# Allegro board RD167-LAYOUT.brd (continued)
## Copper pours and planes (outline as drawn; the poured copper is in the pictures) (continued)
HV_DC_P on CONDUCTIVE5: outline of 196 points within 1,1 132.5,263 ; 26 cut-outs
LV_DC_N on BOTTOM (solid shape): 226.31,61.38 226.18,62.07 226.87,62.21 228.11,61.38 228.34,60.96 228.11,60.55 226.87,59.72 226.36,59.69 226.09,60.13 226.15,60.37 226.31,60.55 226.4,60.61 226.4,61.32
LV_DC_N on BOTTOM (solid shape): 226.31,28.38 226.18,29.07 226.87,29.21 228.11,28.38 228.34,27.96 228.11,27.55 226.87,26.72 226.36,26.69 226.09,27.13 226.15,27.37 226.31,27.55 226.4,27.61 226.4,28.32
LV_DC_N on BOTTOM (solid shape): 257.31,61.38 257.18,62.07 257.87,62.21 259.11,61.38 259.34,60.96 259.11,60.55 257.87,59.72 257.36,59.69 257.09,60.13 257.15,60.37 257.31,60.55 257.4,60.61 257.4,61.32
LV_DC_N on BOTTOM (solid shape): 257.31,28.38 257.18,29.07 257.87,29.21 259.11,28.38 259.34,27.96 259.11,27.55 257.87,26.72 257.36,26.69 257.09,27.13 257.15,27.37 257.31,27.55 257.4,27.61 257.4,28.32
LV_DC_N on BOTTOM (solid shape): 288.31,61.38 288.18,62.07 288.87,62.21 290.11,61.38 290.34,60.96 290.11,60.55 288.87,59.72 288.36,59.69 288.09,60.13 288.15,60.37 288.31,60.55 288.4,60.61 288.4,61.32
LV_DC_N on BOTTOM (solid shape): 288.31,28.38 288.18,29.07 288.87,29.21 290.11,28.38 290.34,27.96 290.11,27.55 288.87,26.72 288.36,26.69 288.09,27.13 288.15,27.37 288.31,27.55 288.4,27.61 288.4,28.32
LV_DC_N on BOTTOM (solid shape): 225.83,62.15 225.98,61.8 225.92,61.56 225.76,61.38 225.67,61.32 225.67,60.61 225.76,60.55 225.9,59.86 225.2,59.72 223.96,60.55 223.74,60.96 223.96,61.38 225.2,62.21 225.33,62.27 225.48,62.3
LV_DC_N on BOTTOM (solid shape): 225.83,29.15 225.98,28.8 225.92,28.56 225.76,28.38 225.67,28.32 225.67,27.61 225.76,27.55 225.9,26.86 225.2,26.72 223.96,27.55 223.74,27.96 223.96,28.38 225.2,29.21 225.33,29.27 225.48,29.3
LV_DC_N on BOTTOM (solid shape): 225.62,63.04 226.04,63.26 226.45,63.04 227.28,61.8 227.35,61.67 227.37,61.52 227.22,61.17 226.87,61.02 226.63,61.08 226.45,61.24 226.39,61.33 225.68,61.33 225.62,61.24 224.93,61.1 224.79,61.8
LV_DC_N on BOTTOM (solid shape): 225.62,30.04 226.04,30.26 226.45,30.04 227.28,28.8 227.35,28.67 227.37,28.52 227.22,28.17 226.87,28.02 226.63,28.08 226.45,28.24 226.39,28.33 225.68,28.33 225.62,28.24 224.93,28.1 224.79,28.8
LV_DC_N on BOTTOM (solid shape): 256.83,62.15 256.98,61.8 256.92,61.56 256.76,61.38 256.67,61.32 256.67,60.61 256.76,60.55 256.9,59.86 256.2,59.72 254.96,60.55 254.74,60.96 254.96,61.38 256.2,62.21 256.33,62.27 256.48,62.3
LV_DC_N on BOTTOM (solid shape): 256.83,29.15 256.98,28.8 256.92,28.56 256.76,28.38 256.67,28.32 256.67,27.61 256.76,27.55 256.9,26.86 256.2,26.72 254.96,27.55 254.74,27.96 254.96,28.38 256.2,29.21 256.33,29.27 256.48,29.3
LV_DC_N on BOTTOM (solid shape): 256.62,63.04 257.04,63.26 257.45,63.04 258.28,61.8 258.35,61.67 258.37,61.52 258.22,61.17 257.87,61.02 257.63,61.08 257.45,61.24 257.39,61.33 256.68,61.33 256.62,61.24 255.93,61.1 255.79,61.8
LV_DC_N on BOTTOM (solid shape): 256.62,30.04 257.04,30.26 257.45,30.04 258.28,28.8 258.35,28.67 258.37,28.52 258.22,28.17 257.87,28.02 257.63,28.08 257.45,28.24 257.39,28.33 256.68,28.33 256.62,28.24 255.93,28.1 255.79,28.8
LV_DC_N on BOTTOM (solid shape): 287.83,62.15 287.98,61.8 287.92,61.56 287.76,61.38 287.67,61.32 287.67,60.61 287.76,60.55 287.9,59.86 287.2,59.72 285.96,60.55 285.74,60.96 285.96,61.38 287.2,62.21 287.33,62.27 287.48,62.3
LV_DC_N on BOTTOM (solid shape): 287.83,29.15 287.98,28.8 287.92,28.56 287.76,28.38 287.67,28.32 287.67,27.61 287.76,27.55 287.9,26.86 287.2,26.72 285.96,27.55 285.74,27.96 285.96,28.38 287.2,29.21 287.33,29.27 287.48,29.3
LV_DC_N on BOTTOM (solid shape): 287.62,63.04 288.04,63.26 288.45,63.04 289.28,61.8 289.35,61.67 289.37,61.52 289.22,61.17 288.87,61.02 288.63,61.08 288.45,61.24 288.39,61.33 287.68,61.33 287.62,61.24 286.93,61.1 286.79,61.8
LV_DC_N on BOTTOM (solid shape): 287.62,30.04 288.04,30.26 288.45,30.04 289.28,28.8 289.35,28.67 289.37,28.52 289.22,28.17 288.87,28.02 288.63,28.08 288.45,28.24 288.39,28.33 287.68,28.33 287.62,28.24 286.93,28.1 286.79,28.8
LV_DC_N on CONDUCTIVE3 (solid shape): 225.14,60.96 225.7,60.75 225.74,60.68 226.33,60.68 226.37,60.75 227.06,60.9 227.22,60.21 226.46,59.02 226.04,58.78 225.61,59.02 224.85,60.21 224.8,60.34 224.78,60.48
LV_DC_N on CONDUCTIVE3 (solid shape): 225.29,62.15 225.98,61.99 225.82,61.3 225.75,61.26 225.75,60.67 225.82,60.63 225.98,59.94 225.29,59.78 224.09,60.54 223.86,60.96 224.09,61.39
LV_DC_N on CONDUCTIVE3 (solid shape): 225.29,29.15 225.98,28.99 225.82,28.3 225.75,28.26 225.75,27.67 225.82,27.63 225.98,26.94 225.29,26.78 224.09,27.54 223.86,27.96 224.09,28.39
LV_DC_N on CONDUCTIVE3 (solid shape): 226.25,61.3 226.1,61.99 226.79,62.15 227.98,61.39 228.22,60.96 227.98,60.54 226.79,59.78 226.1,59.94 226.25,60.63 226.32,60.67 226.32,61.26
LV_DC_N on CONDUCTIVE3 (solid shape): 226.25,28.3 226.1,28.99 226.79,29.15 227.98,28.39 228.22,27.96 227.98,27.54 226.79,26.78 226.1,26.94 226.25,27.63 226.32,27.67 226.32,28.26
LV_DC_N on CONDUCTIVE3 (solid shape): 256.14,60.96 256.7,60.75 256.74,60.68 257.33,60.68 257.37,60.75 258.06,60.9 258.22,60.21 257.46,59.02 257.04,58.78 256.61,59.02 255.85,60.21 255.8,60.34 255.78,60.48
LV_DC_N on CONDUCTIVE3 (solid shape): 256.29,62.15 256.98,61.99 256.82,61.3 256.75,61.26 256.75,60.67 256.82,60.63 256.98,59.94 256.29,59.78 255.09,60.54 254.86,60.96 255.09,61.39
LV_DC_N on CONDUCTIVE3 (solid shape): 256.29,29.15 256.98,28.99 256.82,28.3 256.75,28.26 256.75,27.67 256.82,27.63 256.98,26.94 256.29,26.78 255.09,27.54 254.86,27.96 255.09,28.39
LV_DC_N on CONDUCTIVE3 (solid shape): 257.25,61.3 257.1,61.99 257.79,62.15 258.98,61.39 259.22,60.96 258.98,60.54 257.79,59.78 257.1,59.94 257.25,60.63 257.32,60.67 257.32,61.26
LV_DC_N on CONDUCTIVE3 (solid shape): 257.25,28.3 257.1,28.99 257.79,29.15 258.98,28.39 259.22,27.96 258.98,27.54 257.79,26.78 257.1,26.94 257.25,27.63 257.32,27.67 257.32,28.26
LV_DC_N on CONDUCTIVE3 (solid shape): 287.14,60.96 287.7,60.75 287.74,60.68 288.33,60.68 288.37,60.75 289.06,60.9 289.22,60.21 288.46,59.02 288.04,58.78 287.61,59.02 286.85,60.21 286.8,60.34 286.78,60.48
LV_DC_N on CONDUCTIVE3 (solid shape): 287.29,62.15 287.98,61.99 287.82,61.3 287.75,61.26 287.75,60.67 287.82,60.63 287.98,59.94 287.29,59.78 286.09,60.54 285.86,60.96 286.09,61.39
LV_DC_N on CONDUCTIVE3 (solid shape): 287.29,29.15 287.98,28.99 287.82,28.3 287.75,28.26 287.75,27.67 287.82,27.63 287.98,26.94 287.29,26.78 286.09,27.54 285.86,27.96 286.09,28.39
LV_DC_N on CONDUCTIVE3 (solid shape): 288.25,61.3 288.1,61.99 288.79,62.15 289.98,61.39 290.22,60.96 289.98,60.54 288.79,59.78 288.1,59.94 288.25,60.63 288.32,60.67 288.32,61.26
LV_DC_N on CONDUCTIVE3 (solid shape): 288.25,28.3 288.1,28.99 288.79,29.15 289.98,28.39 290.22,27.96 289.98,27.54 288.79,26.78 288.1,26.94 288.25,27.63 288.32,27.67 288.32,28.26
LV_DC_N on CONDUCTIVE3 (solid shape): 225.61,62.91 226.04,63.14 226.46,62.91 227.22,61.71 227.28,61.59 227.3,61.45 227.15,61.09 226.8,60.95 226.55,61.01 226.37,61.18 226.33,61.25 225.74,61.25 225.7,61.18 225.01,61.02 224.85,61.71
LV_DC_N on CONDUCTIVE3 (solid shape): 256.61,62.91 257.04,63.14 257.46,62.91 258.22,61.71 258.28,61.59 258.3,61.45 258.15,61.09 257.8,60.95 257.55,61.01 257.37,61.18 257.33,61.25 256.74,61.25 256.7,61.18 256.01,61.02 255.85,61.71
LV_DC_N on CONDUCTIVE3 (solid shape): 287.61,62.91 288.04,63.14 288.46,62.91 289.22,61.71 289.28,61.59 289.3,61.45 289.15,61.09 288.8,60.95 288.55,61.01 288.37,61.18 288.33,61.25 287.74,61.25 287.7,61.18 287.01,61.02 286.85,61.71
LV_DC_N on TOP: 269.5,260.75 269.57,260.93 269.75,261 274.32,261 274.48,260.94 274.56,260.79 276.22,258.22 279.21,257.56 279.41,257.51 279.5,257.32 279.5,195.68 279.41,195.49 279.21,195.44 274.5,191.5 279.21,187.56 279.41,187.51 279.5,187.32 279.5,177.68 279.41,177.49 279.21,177.44 274.5,173.5 279.21,169.56 279.41,169.51 279.5,169.32 279.5,117.5 279.43,117.32 279.25,117.25 269.75,117.25 269.57,117.32 269.5,117.5 ; 12 cut-outs
LV_DC_N on BOTTOM: outline of 366 points within 196.37,0.5 319.5,261.25 ; 34 cut-outs
LV_DC_N on CONDUCTIVE5: outline of 141 points within 205.5,118 237,135 ; 6 cut-outs
LV_DC_N on CONDUCTIVE5: outline of 134 points within 205.5,206 237,223 ; 6 cut-outs
LV_DC_P on CONDUCTIVE2 (solid shape): 218.07,68.03 218.63,67.82 218.67,67.75 219.26,67.75 219.3,67.82 219.99,67.98 220.15,67.29 219.39,66.09 218.96,65.86 218.54,66.09 217.78,67.29 217.72,67.41 217.7,67.55
LV_DC_P on CONDUCTIVE2 (solid shape): 218.07,35.03 218.63,34.82 218.67,34.75 219.26,34.75 219.3,34.82 219.99,34.98 220.15,34.29 219.39,33.09 218.96,32.86 218.54,33.09 217.78,34.29 217.72,34.41 217.7,34.55
LV_DC_P on CONDUCTIVE2 (solid shape): 219.18,68.37 219.02,69.06 219.71,69.22 220.91,68.46 221.14,68.04 220.91,67.61 219.71,66.85 219.02,67.01 219.18,67.7 219.25,67.74 219.25,68.33
LV_DC_P on CONDUCTIVE2 (solid shape): 219.18,35.37 219.02,36.06 219.71,36.22 220.91,35.46 221.14,35.04 220.91,34.61 219.71,33.85 219.02,34.01 219.18,34.7 219.25,34.74 219.25,35.33
LV_DC_P on CONDUCTIVE2 (solid shape): 249.07,68.03 249.63,67.82 249.67,67.75 250.26,67.75 250.3,67.82 250.99,67.98 251.15,67.29 250.39,66.09 249.96,65.86 249.54,66.09 248.78,67.29 248.72,67.41 248.7,67.55
LV_DC_P on CONDUCTIVE2 (solid shape): 249.07,35.03 249.63,34.82 249.67,34.75 250.26,34.75 250.3,34.82 250.99,34.98 251.15,34.29 250.39,33.09 249.96,32.86 249.54,33.09 248.78,34.29 248.72,34.41 248.7,34.55
LV_DC_P on CONDUCTIVE2 (solid shape): 250.18,68.37 250.02,69.06 250.71,69.22 251.91,68.46 252.14,68.04 251.91,67.61 250.71,66.85 250.02,67.01 250.18,67.7 250.25,67.74 250.25,68.33
LV_DC_P on CONDUCTIVE2 (solid shape): 250.18,35.37 250.02,36.06 250.71,36.22 251.91,35.46 252.14,35.04 251.91,34.61 250.71,33.85 250.02,34.01 250.18,34.7 250.25,34.74 250.25,35.33
LV_DC_P on CONDUCTIVE2 (solid shape): 280.07,68.03 280.63,67.82 280.67,67.75 281.26,67.75 281.3,67.82 281.99,67.98 282.15,67.29 281.39,66.09 280.96,65.86 280.54,66.09 279.78,67.29 279.72,67.41 279.7,67.55
LV_DC_P on CONDUCTIVE2 (solid shape): 280.07,35.03 280.63,34.82 280.67,34.75 281.26,34.75 281.3,34.82 281.99,34.98 282.15,34.29 281.39,33.09 280.96,32.86 280.54,33.09 279.78,34.29 279.72,34.41 279.7,34.55
LV_DC_P on CONDUCTIVE2 (solid shape): 281.18,68.37 281.02,69.06 281.71,69.22 282.91,68.46 283.14,68.04 282.91,67.61 281.71,66.85 281.02,67.01 281.18,67.7 281.25,67.74 281.25,68.33
LV_DC_P on CONDUCTIVE2 (solid shape): 281.18,35.37 281.02,36.06 281.71,36.22 282.91,35.46 283.14,35.04 282.91,34.61 281.71,33.85 281.02,34.01 281.18,34.7 281.25,34.74 281.25,35.33
LV_DC_P on CONDUCTIVE2 (solid shape): 218.54,69.98 218.96,70.22 219.39,69.98 220.15,68.79 220.2,68.66 220.22,68.52 220.08,68.16 219.72,68.02 219.48,68.08 219.3,68.25 219.26,68.32 218.67,68.32 218.63,68.25 217.94,68.1 217.78,68.79
LV_DC_P on CONDUCTIVE2 (solid shape): 218.54,36.98 218.96,37.22 219.39,36.98 220.15,35.79 220.2,35.66 220.22,35.52 220.08,35.16 219.72,35.02 219.48,35.08 219.3,35.25 219.26,35.32 218.67,35.32 218.63,35.25 217.94,35.1 217.78,35.79
LV_DC_P on CONDUCTIVE2 (solid shape): 249.54,69.98 249.96,70.22 250.39,69.98 251.15,68.79 251.2,68.66 251.22,68.52 251.08,68.16 250.72,68.02 250.48,68.08 250.3,68.25 250.26,68.32 249.67,68.32 249.63,68.25 248.94,68.1 248.78,68.79
LV_DC_P on CONDUCTIVE2 (solid shape): 249.54,36.98 249.96,37.22 250.39,36.98 251.15,35.79 251.2,35.66 251.22,35.52 251.08,35.16 250.72,35.02 250.48,35.08 250.3,35.25 250.26,35.32 249.67,35.32 249.63,35.25 248.94,35.1 248.78,35.79
LV_DC_P on CONDUCTIVE2 (solid shape): 280.54,69.98 280.96,70.22 281.39,69.98 282.15,68.79 282.2,68.66 282.22,68.52 282.08,68.16 281.72,68.02 281.48,68.08 281.3,68.25 281.26,68.32 280.67,68.32 280.63,68.25 279.94,68.1 279.78,68.79
LV_DC_P on CONDUCTIVE2 (solid shape): 280.54,36.98 280.96,37.22 281.39,36.98 282.15,35.79 282.2,35.66 282.22,35.52 282.08,35.16 281.72,35.02 281.48,35.08 281.3,35.25 281.26,35.32 280.67,35.32 280.63,35.25 279.94,35.1 279.78,35.79
LV_DC_P on CONDUCTIVE5 (solid shape): 218.07,68.03 218.63,67.82 218.67,67.75 219.26,67.75 219.3,67.82 219.99,67.98 220.15,67.29 219.39,66.09 218.96,65.86 218.54,66.09 217.78,67.29 217.72,67.41 217.7,67.55
LV_DC_P on CONDUCTIVE5 (solid shape): 218.07,35.03 218.63,34.82 218.67,34.75 219.26,34.75 219.3,34.82 219.99,34.98 220.15,34.29 219.39,33.09 218.96,32.86 218.54,33.09 217.78,34.29 217.72,34.41 217.7,34.55
LV_DC_P on CONDUCTIVE5 (solid shape): 219.18,68.37 219.02,69.06 219.71,69.22 220.91,68.46 221.14,68.04 220.91,67.61 219.71,66.85 219.02,67.01 219.18,67.7 219.25,67.74 219.25,68.33
LV_DC_P on CONDUCTIVE5 (solid shape): 219.18,35.37 219.02,36.06 219.71,36.22 220.91,35.46 221.14,35.04 220.91,34.61 219.71,33.85 219.02,34.01 219.18,34.7 219.25,34.74 219.25,35.33
LV_DC_P on CONDUCTIVE5 (solid shape): 249.07,68.03 249.63,67.82 249.67,67.75 250.26,67.75 250.3,67.82 250.99,67.98 251.15,67.29 250.39,66.09 249.96,65.86 249.54,66.09 248.78,67.29 248.72,67.41 248.7,67.55
LV_DC_P on CONDUCTIVE5 (solid shape): 249.07,35.03 249.63,34.82 249.67,34.75 250.26,34.75 250.3,34.82 250.99,34.98 251.15,34.29 250.39,33.09 249.96,32.86 249.54,33.09 248.78,34.29 248.72,34.41 248.7,34.55
LV_DC_P on CONDUCTIVE5 (solid shape): 250.18,68.37 250.02,69.06 250.71,69.22 251.91,68.46 252.14,68.04 251.91,67.61 250.71,66.85 250.02,67.01 250.18,67.7 250.25,67.74 250.25,68.33
LV_DC_P on CONDUCTIVE5 (solid shape): 250.18,35.37 250.02,36.06 250.71,36.22 251.91,35.46 252.14,35.04 251.91,34.61 250.71,33.85 250.02,34.01 250.18,34.7 250.25,34.74 250.25,35.33
LV_DC_P on CONDUCTIVE5 (solid shape): 280.07,68.03 280.63,67.82 280.67,67.75 281.26,67.75 281.3,67.82 281.99,67.98 282.15,67.29 281.39,66.09 280.96,65.86 280.54,66.09 279.78,67.29 279.72,67.41 279.7,67.55
LV_DC_P on CONDUCTIVE5 (solid shape): 280.07,35.03 280.63,34.82 280.67,34.75 281.26,34.75 281.3,34.82 281.99,34.98 282.15,34.29 281.39,33.09 280.96,32.86 280.54,33.09 279.78,34.29 279.72,34.41 279.7,34.55
LV_DC_P on CONDUCTIVE5 (solid shape): 281.18,68.37 281.02,69.06 281.71,69.22 282.91,68.46 283.14,68.04 282.91,67.61 281.71,66.85 281.02,67.01 281.18,67.7 281.25,67.74 281.25,68.33
LV_DC_P on CONDUCTIVE5 (solid shape): 281.18,35.37 281.02,36.06 281.71,36.22 282.91,35.46 283.14,35.04 282.91,34.61 281.71,33.85 281.02,34.01 281.18,34.7 281.25,34.74 281.25,35.33
LV_DC_P on CONDUCTIVE5 (solid shape): 218.54,69.98 218.96,70.22 219.39,69.98 220.15,68.79 220.2,68.66 220.22,68.52 220.08,68.16 219.72,68.02 219.48,68.08 219.3,68.25 219.26,68.32 218.67,68.32 218.63,68.25 217.94,68.1 217.78,68.79
LV_DC_P on CONDUCTIVE5 (solid shape): 218.54,36.98 218.96,37.22 219.39,36.98 220.15,35.79 220.2,35.66 220.22,35.52 220.08,35.16 219.72,35.02 219.48,35.08 219.3,35.25 219.26,35.32 218.67,35.32 218.63,35.25 217.94,35.1 217.78,35.79
LV_DC_P on CONDUCTIVE5 (solid shape): 249.54,69.98 249.96,70.22 250.39,69.98 251.15,68.79 251.2,68.66 251.22,68.52 251.08,68.16 250.72,68.02 250.48,68.08 250.3,68.25 250.26,68.32 249.67,68.32 249.63,68.25 248.94,68.1 248.78,68.79
LV_DC_P on CONDUCTIVE5 (solid shape): 249.54,36.98 249.96,37.22 250.39,36.98 251.15,35.79 251.2,35.66 251.22,35.52 251.08,35.16 250.72,35.02 250.48,35.08 250.3,35.25 250.26,35.32 249.67,35.32 249.63,35.25 248.94,35.1 248.78,35.79
LV_DC_P on CONDUCTIVE5 (solid shape): 280.54,69.98 280.96,70.22 281.39,69.98 282.15,68.79 282.2,68.66 282.22,68.52 282.08,68.16 281.72,68.02 281.48,68.08 281.3,68.25 281.26,68.32 280.67,68.32 280.63,68.25 279.94,68.1 279.78,68.79
LV_DC_P on CONDUCTIVE5 (solid shape): 280.54,36.98 280.96,37.22 281.39,36.98 282.15,35.79 282.2,35.66 282.22,35.52 282.08,35.16 281.72,35.02 281.48,35.08 281.3,35.25 281.26,35.32 280.67,35.32 280.63,35.25 279.94,35.1 279.78,35.79
LV_DC_P on TOP: outline of 98 points within 227.5,120.5 247.5,260.75 ; 11 cut-outs
LV_DC_P on CONDUCTIVE2: outline of 104 points within 187.5,1 319,95 ; 12 cut-outs
LV_DC_P on CONDUCTIVE5: outline of 181 points within 187.5,1 319,261.25 ; 25 cut-outs
N15594553 on TOP: 83.41,106.25 83.35,106.26 83.31,106.29 82.89,106.71 82.86,106.75 82.85,106.81 82.85,108.19 82.86,108.25 82.89,108.29 83.31,108.71 83.35,108.74 83.41,108.75 87.69,108.75 87.75,108.74 87.79,108.71 87.96,108.54 87.99,108.5 88,108.44 88,106.56 87.99,106.5 87.96,106.46 87.79,106.29 87.75,106.26 87.69,106.25
N15594553 on BOTTOM: 83.56,106.25 83.5,106.26 83.46,106.29 82.79,106.96 82.76,107 82.75,107.06 82.75,108.21 82.76,108.27 82.79,108.32 83.21,108.73 83.25,108.76 83.31,108.78 83.8,108.78 84.31,108.86 84.8,109.14 84.85,109.15 84.92,109.15 85.24,109.46 85.53,109.8 85.78,110.13 86,110.49 86.02,110.52 87,111.5 87,116.25 86.54,116.71 86.51,116.75 86.5,116.81 86.5,117.27 86.51,117.33 86.54,117.38 86.62,117.46 86.67,117.49 86.73,117.5 88.35,117.5 88.46,117.46 88.5,117.35 88.5,110.5 89.25,109.75 92.25,109.75 93.71,111.21 93.75,111.24 93.81,111.25 94.85,111.25 94.96,111.21 95,111.1 95,108.5 95.5,108 96.35,108 96.46,107.96 96.5,107.85 96.5,107.65 96.46,107.54 96.35,107.5 95.5,107.5 94.43,106.43 94.33,106.39 94.22,106.43 91.4,107.5 88.64,106.3 88.59,106.26 88.53,106.25
N15594563 on TOP: 80.81,149.75 80.75,149.76 80.71,149.79 80.29,150.21 80.26,150.25 80.25,150.31 80.25,151.69 80.26,151.75 80.29,151.79 80.71,152.21 80.75,152.24 80.81,152.25 81.51,152.25 81.67,152.23 81.8,152.22 83.8,152.22 83.93,152.23 84.09,152.25 84.69,152.25 84.75,152.24 84.79,152.21 84.96,152.04 84.99,152 85,151.94 85,150.06 84.99,150 84.96,149.96 84.79,149.79 84.75,149.76 84.69,149.75 84.09,149.75 83.93,149.77 83.8,149.78 81.8,149.78 81.67,149.77 81.51,149.75
N15594563 on BOTTOM: 104.06,109.35 104,109.36 103.96,109.39 103.54,109.81 103.51,109.85 103.5,109.91 103.5,114.8 103.51,114.86 103.57,114.97 103.63,115.03 103.69,115.14 103.7,115.2 103.7,116.6 103.71,116.66 103.77,116.77 104.25,117.25 104.25,118.5 103.25,119.5 100.48,119.5 100.04,119.41 99.66,119.16 99.04,118.54 99,118.51 98.94,118.5 86.35,118.5 86.35,118.5 85.92,118.41 84.68,117.29 84.63,117.26 84.57,117.25 83.41,117.25 83.35,117.26 83.31,117.29 82.89,117.71 82.86,117.75 82.85,117.81 82.85,119.19 82.86,119.25 82.89,119.29 84.56,120.96 84.6,120.99 84.66,121 104.11,121 104.17,120.99 104.22,120.96 105.59,119.59 106.24,119.15 107,119 113.19,119 113.25,118.99 113.29,118.96 113.46,118.79 113.49,118.75 113.5,118.69 113.5,118.15 113.46,118.04 113.35,118 110.91,118 110.85,118.01 110.81,118.04 110.5,118.35 106,118.35 105.5,117.85 105.5,110.83 105.49,110.78 105.45,110.72 105.45,110.7 105.45,109.56 105.44,109.5 105.41,109.46 105.34,109.39 105.3,109.36 105.24,109.35
N15594563 on CONDUCTIVE2: outline of 133 points within 1,117.25 85.25,279 ; 16 cut-outs
N15594563 on CONDUCTIVE3, CONDUCTIVE4: outline of 134 points within 1,117.25 85.25,279 ; 16 cut-outs
N15594563 on CONDUCTIVE5: outline of 147 points within 83,104 114.5,121 ; 6 cut-outs
N15594591 on BOTTOM: 101.81,112.25 101.75,112.26 101.71,112.29 101.54,112.46 101.51,112.5 101.5,112.56 101.5,114.94 101.41,115.38 101.16,115.75 101,115.91 100.63,116.16 100.19,116.25 99.66,116.25 99.6,116.26 99.56,116.29 99.18,116.67 99.16,116.7 99.11,116.82 99.1,116.9 99.1,117.1 99.1,117.14 99.12,117.19 99.15,117.23 100.21,118.29 100.37,118.46 100.42,118.49 100.48,118.5 102.6,118.5 102.71,118.46 102.75,118.35 102.75,117.31 102.74,117.25 102.71,117.21 102.3,116.8 102.3,113.6 102.33,113.48 102.37,113.43 102.46,113.34 102.49,113.3 102.5,113.24 102.5,112.56 102.49,112.5 102.46,112.46 102.29,112.29 102.25,112.26 102.19,112.25
N15594597 on BOTTOM: 98.65,107.75 98.54,107.79 98.5,107.9 98.5,114.94 98.51,115 98.54,115.04 98.71,115.21 98.75,115.24 98.81,115.25 100.19,115.25 100.25,115.24 100.29,115.21 100.46,115.04 100.49,115 100.5,114.94 100.5,111.75 101,111.25 102.19,111.25 102.25,111.24 102.29,111.21 102.46,111.04 102.49,111 102.5,110.94 102.5,109.91 102.59,109.47 102.84,109.1 103.25,108.69 103.28,108.66 103.31,108.49 103.17,108.4 102.15,108.4 101.54,107.79 101.5,107.76 101.44,107.75
N15594957 on BOTTOM: 101.81,150.25 101.75,150.26 101.71,150.29 101.54,150.46 101.51,150.5 101.5,150.56 101.5,152.94 101.41,153.38 101.16,153.75 101,153.91 100.63,154.16 100.19,154.25 99.66,154.25 99.6,154.26 99.56,154.29 99.18,154.67 99.16,154.7 99.11,154.82 99.1,154.9 99.1,155.1 99.1,155.14 99.12,155.19 99.15,155.23 100.21,156.29 100.37,156.46 100.42,156.49 100.48,156.5 102.6,156.5 102.71,156.46 102.75,156.35 102.75,155.31 102.74,155.25 102.71,155.21 102.3,154.8 102.3,151.6 102.33,151.48 102.37,151.43 102.46,151.34 102.49,151.3 102.5,151.24 102.5,150.56 102.49,150.5 102.46,150.46 102.29,150.29 102.25,150.26 102.19,150.25
N15595025 on BOTTOM: 98.65,145.75 98.54,145.79 98.5,145.9 98.5,152.94 98.51,153 98.54,153.04 98.71,153.21 98.75,153.24 98.81,153.25 100.19,153.25 100.25,153.24 100.29,153.21 100.46,153.04 100.49,153 100.5,152.94 100.5,149.75 101,149.25 102.19,149.25 102.25,149.24 102.29,149.21 102.46,149.04 102.49,149 102.5,148.94 102.5,147.91 102.59,147.47 102.84,147.1 103.25,146.69 103.28,146.66 103.31,146.49 103.17,146.4 102.15,146.4 101.54,145.79 101.5,145.76 101.44,145.75
N15595027 on TOP: 83.41,144.25 83.35,144.26 83.31,144.29 82.89,144.71 82.86,144.75 82.85,144.81 82.85,146.19 82.86,146.25 82.89,146.29 83.31,146.71 83.35,146.74 83.41,146.75 87.69,146.75 87.75,146.74 87.79,146.71 87.96,146.54 87.99,146.5 88,146.44 88,144.56 87.99,144.5 87.96,144.46 87.79,144.29 87.75,144.26 87.69,144.25
N15595027 on BOTTOM: 83.56,144.25 83.5,144.26 83.46,144.29 82.79,144.96 82.76,145 82.75,145.06 82.75,146.21 82.76,146.27 82.79,146.32 83.21,146.73 83.25,146.76 83.31,146.78 83.8,146.78 84.31,146.86 84.8,147.14 84.85,147.15 84.92,147.15 85.24,147.46 85.53,147.8 85.78,148.13 86,148.49 86.02,148.52 87,149.5 87,154.25 86.54,154.71 86.51,154.75 86.5,154.81 86.5,155.27 86.51,155.33 86.54,155.38 86.62,155.46 86.67,155.49 86.73,155.5 88.35,155.5 88.46,155.46 88.5,155.35 88.5,148.5 89.25,147.75 92.25,147.75 93.71,149.21 93.75,149.24 93.81,149.25 94.85,149.25 94.96,149.21 95,149.1 95,146.5 95.5,146 96.35,146 96.46,145.96 96.5,145.85 96.5,145.65 96.46,145.54 96.35,145.5 95.5,145.5 94.29,144.29 94.25,144.26 94.19,144.25
N15595143 on TOP: 68.5,107.75 68.43,107.57 68.25,107.5 54.75,107.5 54.57,107.57 54.5,107.75 54.5,156.25 54.57,156.43 54.75,156.5 68.25,156.5 68.43,156.43 68.5,156.25 ; 11 cut-outs
N15597681 on TOP: 83.41,194.25 83.35,194.26 83.31,194.29 82.89,194.71 82.86,194.75 82.85,194.81 82.85,196.19 82.86,196.25 82.89,196.29 83.31,196.71 83.35,196.74 83.41,196.75 87.69,196.75 87.75,196.74 87.79,196.71 87.96,196.54 87.99,196.5 88,196.44 88,194.56 87.99,194.5 87.96,194.46 87.79,194.29 87.75,194.26 87.69,194.25
N15597681 on BOTTOM: 83.56,194.25 83.5,194.26 83.46,194.29 82.79,194.96 82.76,195 82.75,195.06 82.75,196.21 82.76,196.27 82.79,196.32 83.21,196.73 83.25,196.76 83.31,196.78 83.8,196.78 84.31,196.86 84.8,197.14 84.85,197.15 84.92,197.15 85.24,197.46 85.53,197.8 85.78,198.13 86,198.49 86.02,198.52 87,199.5 87,204.25 86.54,204.71 86.51,204.75 86.5,204.81 86.5,205.27 86.51,205.33 86.54,205.38 86.62,205.46 86.67,205.49 86.73,205.5 88.35,205.5 88.46,205.46 88.5,205.35 88.5,198.5 89.25,197.75 92.25,197.75 93.71,199.21 93.75,199.24 93.81,199.25 94.85,199.25 94.96,199.21 95,199.1 95,196.5 95.5,196 96.35,196 96.46,195.96 96.5,195.85 96.5,195.65 96.46,195.54 96.35,195.5 95.5,195.5 94.43,194.43 94.33,194.39 94.22,194.43 91.4,195.5 88.64,194.3 88.59,194.26 88.53,194.25
N15597691 on TOP: 80.81,237.75 80.75,237.76 80.71,237.79 80.29,238.21 80.26,238.25 80.25,238.31 80.25,239.69 80.26,239.75 80.29,239.79 80.71,240.21 80.75,240.24 80.81,240.25 81.51,240.25 81.67,240.23 81.8,240.22 83.8,240.22 83.93,240.23 84.09,240.25 84.69,240.25 84.75,240.24 84.79,240.21 84.96,240.04 84.99,240 85,239.94 85,238.06 84.99,238 84.96,237.96 84.79,237.79 84.75,237.76 84.69,237.75 84.09,237.75 83.93,237.77 83.8,237.78 81.8,237.78 81.67,237.77 81.51,237.75
N15597691 on BOTTOM: 104.06,197.35 104,197.36 103.96,197.39 103.54,197.81 103.51,197.85 103.5,197.91 103.5,202.8 103.51,202.86 103.57,202.97 103.63,203.03 103.69,203.14 103.7,203.2 103.7,204.6 103.71,204.66 103.77,204.77 104.25,205.25 104.25,206.5 103.25,207.5 100.48,207.5 100.04,207.41 99.66,207.16 99.04,206.54 99,206.51 98.94,206.5 86.35,206.5 86.35,206.5 85.92,206.41 84.68,205.29 84.63,205.26 84.57,205.25 83.41,205.25 83.35,205.26 83.31,205.29 82.89,205.71 82.86,205.75 82.85,205.81 82.85,207.19 82.86,207.25 82.89,207.29 84.56,208.96 84.6,208.99 84.66,209 104.11,209 104.17,208.99 104.22,208.96 105.59,207.59 106.24,207.15 107,207 113.19,207 113.25,206.99 113.29,206.96 113.46,206.79 113.49,206.75 113.5,206.69 113.5,206.15 113.46,206.04 113.35,206 110.91,206 110.85,206.01 110.81,206.04 110.5,206.35 106,206.35 105.5,205.85 105.5,198.83 105.49,198.78 105.45,198.72 105.45,198.7 105.45,197.56 105.44,197.5 105.41,197.46 105.34,197.39 105.3,197.36 105.24,197.35
N15597691 on CONDUCTIVE2: outline of 107 points within 46.25,205.25 85.25,279 ; 15 cut-outs
N15597691 on CONDUCTIVE3: outline of 115 points within 46.25,205.25 85.25,279 ; 15 cut-outs
N15597691 on CONDUCTIVE4: outline of 110 points within 46.25,205.25 85.25,279 ; 15 cut-outs
N15597691 on CONDUCTIVE5: outline of 147 points within 83,192 114.5,209 ; 6 cut-outs
N15597719 on BOTTOM: 101.81,200.25 101.75,200.26 101.71,200.29 101.54,200.46 101.51,200.5 101.5,200.56 101.5,202.94 101.41,203.38 101.16,203.75 101,203.91 100.63,204.16 100.19,204.25 99.66,204.25 99.6,204.26 99.56,204.29 99.18,204.67 99.16,204.7 99.11,204.82 99.1,204.9 99.1,205.1 99.1,205.14 99.12,205.19 99.15,205.23 100.21,206.29 100.37,206.46 100.42,206.49 100.48,206.5 102.6,206.5 102.71,206.46 102.75,206.35 102.75,205.31 102.74,205.25 102.71,205.21 102.3,204.8 102.3,201.6 102.33,201.48 102.37,201.43 102.46,201.34 102.49,201.3 102.5,201.24 102.5,200.56 102.49,200.5 102.46,200.46 102.29,200.29 102.25,200.26 102.19,200.25
N15597725 on BOTTOM: 98.65,195.75 98.54,195.79 98.5,195.9 98.5,202.94 98.51,203 98.54,203.04 98.71,203.21 98.75,203.24 98.81,203.25 100.19,203.25 100.25,203.24 100.29,203.21 100.46,203.04 100.49,203 100.5,202.94 100.5,199.75 101,199.25 102.19,199.25 102.25,199.24 102.29,199.21 102.46,199.04 102.49,199 102.5,198.94 102.5,197.91 102.59,197.47 102.84,197.1 103.25,196.69 103.28,196.66 103.31,196.49 103.17,196.4 102.15,196.4 101.54,195.79 101.5,195.76 101.44,195.75
N15598085 on BOTTOM: 101.81,238.25 101.75,238.26 101.71,238.29 101.54,238.46 101.51,238.5 101.5,238.56 101.5,240.94 101.41,241.38 101.16,241.75 101,241.91 100.63,242.16 100.19,242.25 99.66,242.25 99.6,242.26 99.56,242.29 99.18,242.67 99.16,242.7 99.11,242.82 99.1,242.9 99.1,243.1 99.1,243.14 99.12,243.19 99.15,243.23 100.21,244.29 100.37,244.46 100.42,244.49 100.48,244.5 102.6,244.5 102.71,244.46 102.75,244.35 102.75,243.31 102.74,243.25 102.71,243.21 102.3,242.8 102.3,239.6 102.33,239.48 102.37,239.43 102.46,239.34 102.49,239.3 102.5,239.24 102.5,238.56 102.49,238.5 102.46,238.46 102.29,238.29 102.25,238.26 102.19,238.25
N15598153 on BOTTOM: 98.65,233.75 98.54,233.79 98.5,233.9 98.5,240.94 98.51,241 98.54,241.04 98.71,241.21 98.75,241.24 98.81,241.25 100.19,241.25 100.25,241.24 100.29,241.21 100.46,241.04 100.49,241 100.5,240.94 100.5,237.75 101,237.25 102.19,237.25 102.25,237.24 102.29,237.21 102.46,237.04 102.49,237 102.5,236.94 102.5,235.91 102.59,235.47 102.84,235.1 103.25,234.69 103.28,234.66 103.31,234.49 103.17,234.4 102.15,234.4 101.54,233.79 101.5,233.76 101.44,233.75
N15598155 on TOP: 83.41,232.25 83.35,232.26 83.31,232.29 82.89,232.71 82.86,232.75 82.85,232.81 82.85,234.19 82.86,234.25 82.89,234.29 83.31,234.71 83.35,234.74 83.41,234.75 87.69,234.75 87.75,234.74 87.79,234.71 87.96,234.54 87.99,234.5 88,234.44 88,232.56 87.99,232.5 87.96,232.46 87.79,232.29 87.75,232.26 87.69,232.25
N15598155 on BOTTOM: 83.56,232.25 83.5,232.26 83.46,232.29 82.79,232.96 82.76,233 82.75,233.06 82.75,234.21 82.76,234.27 82.79,234.32 83.21,234.73 83.25,234.76 83.31,234.78 83.8,234.78 84.31,234.86 84.8,235.14 84.85,235.15 84.92,235.15 85.24,235.46 85.53,235.8 85.78,236.13 86,236.49 86.02,236.52 87,237.5 87,242.25 86.54,242.71 86.51,242.75 86.5,242.81 86.5,243.27 86.51,243.33 86.54,243.38 86.62,243.46 86.67,243.49 86.73,243.5 88.35,243.5 88.46,243.46 88.5,243.35 88.5,236.5 89.25,235.75 92.25,235.75 93.71,237.21 93.75,237.24 93.81,237.25 94.85,237.25 94.96,237.21 95,237.1 95,234.5 95.5,234 96.35,234 96.46,233.96 96.5,233.85 96.5,233.65 96.46,233.54 96.35,233.5 95.5,233.5 94.29,232.29 94.25,232.26 94.19,232.25
N15598271 on TOP: 68.5,195.75 68.43,195.57 68.25,195.5 54.75,195.5 54.57,195.57 54.5,195.75 54.5,244.25 54.57,244.43 54.75,244.5 68.25,244.5 68.43,244.43 68.5,244.25 ; 11 cut-outs
N17096645 on CONDUCTIVE4: 1,89.65 1.02,89.74 1.07,89.82 6.18,94.93 6.26,94.98 6.35,95 103.72,95 103.81,94.98 103.89,94.93 116.08,82.74 116.1,82.72 116.87,81.87 117.72,81.1 117.74,81.08 121.5,77.32 121.55,77.24 121.57,77.15 121.57,45.35 122.92,42.1 126.17,40.75 132.25,40.75 132.43,40.68 132.5,40.5 132.5,19.6 132.48,19.51 132.43,19.43 129.57,16.57 129.49,16.52 129.4,16.5 125,16.5 116.87,13.13 113.5,5 113.5,4.1 113.48,4.01 113.43,3.93 110.57,1.07 110.49,1.02 110.4,1 98.5,1 98.41,1.02 98.33,1.07 95.47,3.93 95.42,4.01 95.4,4.1 95.4,12 93.9,15.57 90.3,17 90.29,17 79.71,17 79.7,17 76.1,15.57 74.6,12 74.6,4.1 74.58,4.01 74.53,3.93 71.67,1.07 71.59,1.02 71.5,1 19.6,1 19.51,1.02 19.43,1.07 16.57,3.93 16.52,4.01 16.5,4.1 16.5,5 13.13,13.13 5,16.5 4.1,16.5 4.01,16.52 3.93,16.57 1.07,19.43 1.02,19.51 1,19.6 ; 21 cut-outs
N17096659 on TOP: 29.25,18 29.07,18.07 29,18.25 29,31.5 29.07,31.68 29.25,31.75 33.75,31.75 33.93,31.68 34,31.5 34,18.25 33.93,18.07 33.75,18
N17096693 on CONDUCTIVE2 (solid shape): 31.07,55.03 31.63,54.82 31.67,54.75 32.26,54.75 32.3,54.82 32.99,54.98 33.15,54.29 32.39,53.09 31.96,52.86 31.54,53.09 30.78,54.29 30.72,54.41 30.7,54.55
N17096693 on CONDUCTIVE2 (solid shape): 32.18,55.37 32.02,56.06 32.71,56.22 33.91,55.46 34.14,55.04 33.91,54.61 32.71,53.85 32.02,54.01 32.18,54.7 32.25,54.74 32.25,55.33
N17096693 on CONDUCTIVE2 (solid shape): 38.14,80.96 38.7,80.75 38.74,80.68 39.33,80.68 39.37,80.75 40.06,80.9 40.22,80.21 39.46,79.02 39.04,78.78 38.61,79.02 37.85,80.21 37.8,80.34 37.78,80.48
N17096693 on CONDUCTIVE2 (solid shape): 38.29,82.15 38.98,81.99 38.82,81.3 38.75,81.26 38.75,80.67 38.82,80.63 38.98,79.94 38.29,79.78 37.09,80.54 36.86,80.96 37.09,81.39
N17096693 on CONDUCTIVE2 (solid shape): 39.25,81.3 39.1,81.99 39.79,82.15 40.98,81.39 41.22,80.96 40.98,80.54 39.79,79.78 39.1,79.94 39.25,80.63 39.32,80.67 39.32,81.26
N17096693 on CONDUCTIVE2 (solid shape): 62.07,55.03 62.63,54.82 62.67,54.75 63.26,54.75 63.3,54.82 63.99,54.98 64.15,54.29 63.39,53.09 62.96,52.86 62.54,53.09 61.78,54.29 61.72,54.41 61.7,54.55
N17096693 on CONDUCTIVE2 (solid shape): 62.21,56.22 62.9,56.06 62.75,55.37 62.68,55.33 62.68,54.74 62.75,54.7 62.9,54.01 62.21,53.85 61.02,54.61 60.78,55.04 61.02,55.46
N17096693 on CONDUCTIVE2 (solid shape): 63.18,55.37 63.02,56.06 63.71,56.22 64.91,55.46 65.14,55.04 64.91,54.61 63.71,53.85 63.02,54.01 63.18,54.7 63.25,54.74 63.25,55.33
N17096693 on CONDUCTIVE2 (solid shape): 69.14,80.96 69.7,80.75 69.74,80.68 70.33,80.68 70.37,80.75 71.06,80.9 71.22,80.21 70.46,79.02 70.04,78.78 69.61,79.02 68.85,80.21 68.8,80.34 68.78,80.48
N17096693 on CONDUCTIVE2 (solid shape): 69.29,82.15 69.98,81.99 69.82,81.3 69.75,81.26 69.75,80.67 69.82,80.63 69.98,79.94 69.29,79.78 68.09,80.54 67.86,80.96 68.09,81.39
N17096693 on CONDUCTIVE2 (solid shape): 70.25,81.3 70.1,81.99 70.79,82.15 71.98,81.39 72.22,80.96 71.98,80.54 70.79,79.78 70.1,79.94 70.25,80.63 70.32,80.67 70.32,81.26
N17096693 on CONDUCTIVE2 (solid shape): 93.07,55.03 93.63,54.82 93.67,54.75 94.26,54.75 94.3,54.82 94.99,54.98 95.15,54.29 94.39,53.09 93.96,52.86 93.54,53.09 92.78,54.29 92.72,54.41 92.7,54.55
N17096693 on CONDUCTIVE2 (solid shape): 100.14,80.96 100.7,80.75 100.74,80.68 101.33,80.68 101.37,80.75 102.06,80.9 102.22,80.21 101.46,79.02 101.04,78.78 100.61,79.02 99.85,80.21 99.8,80.34 99.78,80.48
N17096693 on CONDUCTIVE2 (solid shape): 101.25,81.3 101.1,81.99 101.79,82.15 102.98,81.39 103.22,80.96 102.98,80.54 101.79,79.78 101.1,79.94 101.25,80.63 101.32,80.67 101.32,81.26
N17096693 on CONDUCTIVE2 (solid shape): 31.54,56.98 31.96,57.22 32.39,56.98 33.15,55.79 33.2,55.66 33.22,55.52 33.08,55.16 32.72,55.02 32.48,55.08 32.3,55.25 32.26,55.32 31.67,55.32 31.63,55.25 30.94,55.1 30.78,55.79
N17096693 on CONDUCTIVE2 (solid shape): 38.61,82.91 39.04,83.14 39.46,82.91 40.22,81.71 40.28,81.59 40.3,81.45 40.15,81.09 39.8,80.95 39.55,81.01 39.37,81.18 39.33,81.25 38.74,81.25 38.7,81.18 38.01,81.02 37.85,81.71
N17096693 on CONDUCTIVE2 (solid shape): 62.54,56.98 62.96,57.22 63.39,56.98 64.15,55.79 64.2,55.66 64.22,55.52 64.08,55.16 63.72,55.02 63.48,55.08 63.3,55.25 63.26,55.32 62.67,55.32 62.63,55.25 61.94,55.1 61.78,55.79
N17096693 on CONDUCTIVE2 (solid shape): 69.61,82.91 70.04,83.14 70.46,82.91 71.22,81.71 71.28,81.59 71.3,81.45 71.15,81.09 70.8,80.95 70.55,81.01 70.37,81.18 70.33,81.25 69.74,81.25 69.7,81.18 69.01,81.02 68.85,81.71
N17096693 on CONDUCTIVE2 (solid shape): 93.54,56.98 93.96,57.22 94.39,56.98 95.15,55.79 95.2,55.66 95.22,55.52 95.08,55.16 94.72,55.02 94.48,55.08 94.3,55.25 94.26,55.32 93.67,55.32 93.63,55.25 92.94,55.1 92.78,55.79
N17096693 on CONDUCTIVE2 (solid shape): 94.18,55.37 94.02,56.06 94.71,56.22 95.91,55.46 96.14,55.04 95.91,54.61 94.71,53.85 94.02,54.01 94.18,54.7 94.25,54.74 94.25,55.33
N17096693 on CONDUCTIVE2 (solid shape): 100.61,82.91 101.04,83.14 101.46,82.91 102.22,81.71 102.28,81.59 102.3,81.45 102.15,81.09 101.8,80.95 101.55,81.01 101.37,81.18 101.33,81.25 100.74,81.25 100.7,81.18 100.01,81.02 99.85,81.71
N17096693 on CONDUCTIVE2: outline of 96 points within 1,1 121.75,95 ; 17 cut-outs
N17096757 on TOP: 99.25,18 99.07,18.07 99,18.25 99,31.5 99.07,31.68 99.25,31.75 103.75,31.75 103.93,31.68 104,31.5 104,18.25 103.93,18.07 103.75,18
N17107990 on TOP: 160.25,248.75 157.6,248.75 157.54,248.76 157.43,248.82 156.77,249.48 156.66,249.54 156.6,249.55 155.15,249.55 155.03,249.58 154.93,249.68 154.9,249.8 154.9,250.9 154.93,251.03 155.03,251.12 155.15,251.15 160.25,251.15 160.38,251.12 160.47,251.03 160.5,250.9 160.5,249 160.47,248.88 160.38,248.78 ; 1 cut-out
N17110393 on CONDUCTIVE4: 319,19.6 318.98,19.51 318.93,19.43 316.07,16.57 315.99,16.52 315.9,16.5 315,16.5 306.87,13.13 303.5,5 303.5,4.1 303.48,4.01 303.43,3.93 300.57,1.07 300.49,1.02 300.4,1 252,1 251.91,1.02 251.83,1.07 248.97,3.93 248.92,4.01 248.9,4.1 248.9,12 247.48,15.49 244.01,17 243.9,17 243.8,17 233.2,17 233.19,17 230.79,16.43 228.95,14.79 228.95,14.78 228.32,13.46 228.1,12 228.1,4.1 228.09,4.04 228.03,3.93 225.17,1.07 225.12,1.03 225,1 209.6,1 209.54,1.01 209.43,1.07 206.57,3.93 206.53,3.98 206.5,4.1 206.5,5 205.03,10.63 200.99,14.82 198.11,16.07 195,16.5 187.75,16.5 187.57,16.57 187.5,16.75 187.5,23.65 187.52,23.74 187.57,23.82 190.43,26.68 190.51,26.73 190.6,26.75 193.83,26.75 197.08,28.1 198.43,31.35 198.43,77.08 198.45,77.17 198.5,77.25 202.79,81.54 203.13,81.87 203.46,82.21 216.18,94.93 216.26,94.98 216.35,95 313.65,95 313.74,94.98 313.82,94.93 318.93,89.82 318.98,89.74 319,89.65 ; 18 cut-outs
N17112878 on TOP: 219.48,253.5 219.42,253.51 219.37,253.54 219.25,253.66 218.88,253.91 218.44,254 216.98,254 216.93,254.01 216.87,254.05 216.85,254.05 215.65,254.05 215.54,254.09 215.5,254.2 215.5,255.44 215.51,255.5 215.54,255.54 215.9,255.9 215.9,258.5 215.94,258.61 216.05,258.65 216.6,258.65 216.71,258.61 216.75,258.5 216.83,258.12 217.04,257.79 217.49,257.35 219.3,257.35 219.41,257.31 219.45,257.2 219.45,256.3 220.46,255.29 220.49,255.25 220.5,255.19 220.5,253.81 220.49,253.75 220.46,253.71 220.29,253.54 220.25,253.51 220.19,253.5
N17113118 on TOP: 230.79,212.75 230.75,212.76 230.72,212.78 230,213.5 227.62,213.5 227.54,213.54 227.5,213.62 227.5,214.95 227.51,215 227.54,215.04 227.96,215.46 228,215.49 228.05,215.5 231.45,215.5 231.5,215.49 231.54,215.46 231.75,215.25 235.91,215.25 236.07,215.23 236.2,215.22 238.2,215.22 238.33,215.23 238.49,215.25 239.19,215.25 239.25,215.24 239.29,215.21 239.71,214.79 239.74,214.75 239.75,214.69 239.75,213.31 239.74,213.25 239.71,213.21 239.29,212.79 239.25,212.76 239.19,212.75 238.49,212.75 238.33,212.77 238.2,212.78 236.2,212.78 236.07,212.77 235.91,212.75
N17113118 on BOTTOM: 215.89,244 215.83,244.01 215.78,244.04 214.41,245.41 213.76,245.85 213,246 206.81,246 206.75,246.01 206.71,246.04 206.54,246.21 206.51,246.25 206.5,246.31 206.5,246.85 206.54,246.96 206.65,247 209.09,247 209.15,246.99 209.19,246.96 209.5,246.65 214,246.65 214.5,247.15 214.5,254.17 214.51,254.22 214.55,254.28 214.55,254.3 214.55,255.44 214.56,255.5 214.59,255.54 214.66,255.61 214.7,255.64 214.76,255.65 215.94,255.65 216,255.64 216.04,255.61 216.46,255.19 216.49,255.15 216.5,255.09 216.5,250.2 216.49,250.14 216.43,250.03 216.37,249.97 216.31,249.86 216.3,249.8 216.3,248.4 216.29,248.34 216.23,248.23 215.75,247.75 215.75,246.5 216.75,245.5 219.52,245.5 219.96,245.59 220.34,245.84 220.96,246.46 221,246.49 221.06,246.5 233.65,246.5 233.65,246.5 234.08,246.59 235.32,247.71 235.37,247.74 235.43,247.75 236.59,247.75 236.65,247.74 236.69,247.71 237.11,247.29 237.14,247.25 237.15,247.19 237.15,245.81 237.14,245.75 237.11,245.71 235.44,244.04 235.4,244.01 235.34,244
N17113118 on CONDUCTIVE2: outline of 120 points within 234.75,193.75 273.75,279 ; 15 cut-outs
N17113118 on CONDUCTIVE3: outline of 118 points within 234.75,193.75 273.75,279 ; 15 cut-outs
N17113118 on CONDUCTIVE4: outline of 116 points within 234.75,193.75 273.75,279 ; 15 cut-outs
N17113118 on CONDUCTIVE5: outline of 136 points within 205.5,244 237,261 ; 6 cut-outs
N17113163 on BOTTOM: 217.4,246.5 217.29,246.54 217.25,246.65 217.25,247.69 217.26,247.75 217.29,247.79 217.7,248.2 217.7,251.4 217.67,251.52 217.63,251.57 217.54,251.66 217.51,251.7 217.5,251.76 217.5,252.44 217.51,252.5 217.54,252.54 217.71,252.71 217.75,252.74 217.81,252.75 218.19,252.75 218.25,252.74 218.29,252.71 218.46,252.54 218.49,252.5 218.5,252.44 218.5,250.06 218.59,249.62 218.84,249.25 219,249.09 219.37,248.84 219.81,248.75 220.34,248.75 220.4,248.74 220.44,248.71 220.82,248.33 220.84,248.3 220.89,248.18 220.9,248.1 220.9,247.9 220.9,247.86 220.88,247.81 220.85,247.77 219.79,246.71 219.63,246.54 219.58,246.51 219.52,246.5
N17113250 on BOTTOM: 219.81,249.75 219.75,249.76 219.71,249.79 219.54,249.96 219.51,250 219.5,250.06 219.5,253.25 219,253.75 217.81,253.75 217.75,253.76 217.71,253.79 217.54,253.96 217.51,254 217.5,254.06 217.5,255.09 217.41,255.53 217.16,255.9 216.75,256.31 216.72,256.34 216.69,256.51 216.83,256.6 217.85,256.6 217.89,256.62 217.93,256.62 218.1,256.62 218.38,256.68 218.61,256.84 218.98,257.21 219.03,257.24 219.09,257.25 221.35,257.25 221.46,257.21 221.5,257.1 221.5,250.06 221.49,250 221.46,249.96 221.29,249.79 221.25,249.77 221.22,249.75 221.19,249.75
N17113254 on TOP: 232.31,256.25 232.25,256.26 232.21,256.29 232.04,256.46 232.01,256.5 232,256.56 232,258.44 232.01,258.5 232.04,258.54 232.21,258.71 232.25,258.74 232.31,258.75 236.59,258.75 236.65,258.74 236.69,258.71 237.11,258.29 237.14,258.25 237.15,258.19 237.15,256.81 237.14,256.75 237.11,256.71 236.69,256.29 236.65,256.26 236.59,256.25
N17113254 on BOTTOM: 231.65,247.5 231.54,247.54 231.5,247.65 231.5,254.5 230.75,255.25 227.75,255.25 226.29,253.79 226.25,253.76 226.19,253.75 225.15,253.75 225.04,253.79 225,253.9 225,256.5 224.5,257 223.65,257 223.54,257.04 223.5,257.15 223.5,257.35 223.54,257.46 223.65,257.5 225,257.5 225.58,257.69 225.94,258.17 226.04,258.27 226.17,258.25 228.85,257.52 231.36,258.7 231.41,258.74 231.47,258.75 236.44,258.75 236.5,258.74 236.54,258.71 237.21,258.04 237.24,258 237.25,257.94 237.25,256.79 237.24,256.73 237.21,256.68 236.79,256.27 236.75,256.24 236.69,256.23 236.2,256.23 235.69,256.14 235.2,255.86 235.15,255.85 235.08,255.85 234.76,255.54 234.47,255.2 234.22,254.87 234,254.51 233.98,254.48 233,253.5 233,248.75 233.46,248.29 233.49,248.25 233.5,248.19 233.5,247.73 233.49,247.67 233.46,247.62 233.38,247.54 233.33,247.51 233.27,247.5
N17113532 on TOP: 265.5,208.75 265.43,208.57 265.25,208.5 251.75,208.5 251.57,208.57 251.5,208.75 251.5,257.25 251.57,257.43 251.75,257.5 265.25,257.5 265.43,257.43 265.5,257.25 ; 11 cut-outs
N17113656 on TOP: 219.48,215.5 219.42,215.51 219.37,215.54 219.25,215.66 218.88,215.91 218.44,216 216.98,216 216.93,216.01 216.87,216.05 216.85,216.05 215.65,216.05 215.54,216.09 215.5,216.2 215.5,217.44 215.51,217.5 215.54,217.54 215.9,217.9 215.9,220.5 215.94,220.61 216.05,220.65 216.6,220.65 216.71,220.61 216.75,220.5 216.83,220.12 217.04,219.79 217.49,219.35 219.3,219.35 219.41,219.31 219.45,219.2 219.45,218.3 220.46,217.29 220.49,217.25 220.5,217.19 220.5,215.81 220.49,215.75 220.46,215.71 220.29,215.54 220.25,215.51 220.19,215.5
N17113949 on BOTTOM: 217.4,208.5 217.29,208.54 217.25,208.65 217.25,209.69 217.26,209.75 217.29,209.79 217.7,210.2 217.7,213.4 217.67,213.52 217.63,213.57 217.54,213.66 217.51,213.7 217.5,213.76 217.5,214.44 217.51,214.5 217.54,214.54 217.71,214.71 217.75,214.74 217.81,214.75 218.19,214.75 218.25,214.74 218.29,214.71 218.46,214.54 218.49,214.5 218.5,214.44 218.5,212.06 218.59,211.62 218.84,211.25 219,211.09 219.37,210.84 219.81,210.75 220.34,210.75 220.4,210.74 220.44,210.71 220.82,210.33 220.84,210.3 220.89,210.18 220.9,210.1 220.9,209.9 220.9,209.86 220.88,209.81 220.85,209.77 219.79,208.71 219.63,208.54 219.58,208.51 219.52,208.5
N17114036 on BOTTOM: 219.81,211.75 219.75,211.76 219.71,211.79 219.54,211.96 219.51,212 219.5,212.06 219.5,215.25 219,215.75 217.81,215.75 217.75,215.76 217.71,215.79 217.54,215.96 217.51,216 217.5,216.06 217.5,217.09 217.41,217.53 217.16,217.9 216.75,218.31 216.71,218.36 216.69,218.38 216.68,218.42 216.68,218.47 216.72,218.58 216.83,218.62 218.1,218.62 218.38,218.68 218.61,218.84 218.98,219.21 219.03,219.24 219.09,219.25 221.35,219.25 221.46,219.21 221.5,219.1 221.5,212.06 221.49,212 221.46,211.96 221.29,211.79 221.25,211.76 221.19,211.75
N17114040 on TOP: 232.31,218.25 232.25,218.26 232.21,218.29 232.04,218.46 232.01,218.5 232,218.56 232,220.44 232.01,220.5 232.04,220.54 232.21,220.71 232.25,220.74 232.31,220.75 236.59,220.75 236.65,220.74 236.69,220.71 237.11,220.29 237.14,220.25 237.15,220.19 237.15,218.81 237.14,218.75 237.11,218.71 236.69,218.29 236.65,218.26 236.59,218.25
N17114040 on BOTTOM: 231.65,209.5 231.54,209.54 231.5,209.65 231.5,216.5 230.75,217.25 227.75,217.25 226.29,215.79 226.25,215.76 226.19,215.75 225.15,215.75 225.04,215.79 225,215.9 225,218.5 224.5,219 223.65,219 223.54,219.04 223.5,219.15 223.5,219.35 223.54,219.46 223.65,219.5 225,219.5 225.74,219.82 226.04,220.7 226.15,220.75 236.44,220.75 236.5,220.74 236.54,220.71 237.21,220.04 237.24,220 237.25,219.94 237.25,218.79 237.24,218.73 237.21,218.68 236.79,218.27 236.75,218.24 236.69,218.22 236.2,218.22 235.69,218.14 235.2,217.86 235.15,217.85 235.08,217.85 234.76,217.54 234.47,217.2 234.22,216.87 234,216.51 233.98,216.48 233,215.5 233,210.75 233.46,210.29 233.49,210.25 233.5,210.19 233.5,209.73 233.49,209.67 233.46,209.62 233.38,209.54 233.33,209.51 233.27,209.5
N17116276 on TOP: 219.48,165.5 219.42,165.51 219.37,165.54 219.25,165.66 218.88,165.91 218.44,166 216.98,166 216.93,166.01 216.87,166.05 216.85,166.05 215.65,166.05 215.54,166.09 215.5,166.2 215.5,167.44 215.51,167.5 215.54,167.54 215.9,167.9 215.9,170.5 215.94,170.61 216.05,170.65 216.6,170.65 216.71,170.61 216.75,170.5 216.83,170.12 217.04,169.79 217.49,169.35 219.3,169.35 219.41,169.31 219.45,169.2 219.45,168.3 220.46,167.29 220.49,167.25 220.5,167.19 220.5,165.81 220.49,165.75 220.46,165.71 220.29,165.54 220.25,165.51 220.19,165.5
N17116516 on TOP: 230.79,124.75 230.75,124.76 230.72,124.78 230,125.5 227.62,125.5 227.54,125.54 227.5,125.62 227.5,126.95 227.51,127 227.54,127.04 227.96,127.46 228,127.49 228.05,127.5 231.45,127.5 231.5,127.49 231.54,127.46 231.75,127.25 235.91,127.25 236.07,127.23 236.2,127.22 238.2,127.22 238.33,127.23 238.49,127.25 239.19,127.25 239.25,127.24 239.29,127.21 239.71,126.79 239.74,126.75 239.75,126.69 239.75,125.31 239.74,125.25 239.71,125.21 239.29,124.79 239.25,124.76 239.19,124.75 238.49,124.75 238.33,124.77 238.2,124.78 236.2,124.78 236.07,124.77 235.91,124.75
N17116516 on BOTTOM: 215.89,156 215.83,156.01 215.78,156.04 214.41,157.41 213.76,157.85 213,158 206.81,158 206.75,158.01 206.71,158.04 206.54,158.21 206.51,158.25 206.5,158.31 206.5,158.85 206.54,158.96 206.65,159 209.09,159 209.15,158.99 209.19,158.96 209.5,158.65 214,158.65 214.5,159.15 214.5,166.17 214.51,166.22 214.55,166.28 214.55,166.3 214.55,167.44 214.56,167.5 214.59,167.54 214.66,167.61 214.7,167.64 214.76,167.65 215.94,167.65 216,167.64 216.04,167.61 216.46,167.19 216.49,167.15 216.5,167.09 216.5,162.2 216.49,162.14 216.43,162.03 216.37,161.97 216.31,161.86 216.3,161.8 216.3,160.4 216.29,160.34 216.23,160.23 215.75,159.75 215.75,158.5 216.75,157.5 219.52,157.5 219.96,157.59 220.34,157.84 220.96,158.46 221,158.49 221.06,158.5 233.65,158.5 233.65,158.5 234.08,158.59 235.32,159.71 235.37,159.74 235.43,159.75 236.59,159.75 236.65,159.74 236.69,159.71 237.11,159.29 237.14,159.25 237.15,159.19 237.15,157.81 237.14,157.75 237.11,157.71 235.44,156.04 235.4,156.01 235.34,156
N17116516 on CONDUCTIVE2: outline of 143 points within 234.75,105.75 319,279 ; 14 cut-outs
N17116516 on CONDUCTIVE3: outline of 145 points within 234.75,105.75 319,279 ; 14 cut-outs
N17116516 on CONDUCTIVE4: outline of 141 points within 234.75,105.75 319,279 ; 14 cut-outs
N17116516 on CONDUCTIVE5: outline of 138 points within 205.5,156 237,173 ; 6 cut-outs
N17116561 on BOTTOM: 217.4,158.5 217.29,158.54 217.25,158.65 217.25,159.69 217.26,159.75 217.29,159.79 217.7,160.2 217.7,163.4 217.67,163.52 217.63,163.57 217.54,163.66 217.51,163.7 217.5,163.76 217.5,164.44 217.51,164.5 217.54,164.54 217.71,164.71 217.75,164.74 217.81,164.75 218.19,164.75 218.25,164.74 218.29,164.71 218.46,164.54 218.49,164.5 218.5,164.44 218.5,162.06 218.59,161.62 218.84,161.25 219,161.09 219.37,160.84 219.81,160.75 220.34,160.75 220.4,160.74 220.44,160.71 220.82,160.33 220.84,160.3 220.89,160.18 220.9,160.1 220.9,159.9 220.9,159.86 220.88,159.81 220.85,159.77 219.79,158.71 219.63,158.54 219.58,158.51 219.52,158.5
N17116648 on BOTTOM: 219.81,161.75 219.75,161.76 219.71,161.79 219.54,161.96 219.51,162 219.5,162.06 219.5,165.25 219,165.75 217.81,165.75 217.75,165.76 217.71,165.79 217.54,165.96 217.51,166 217.5,166.06 217.5,167.09 217.41,167.53 217.16,167.9 216.75,168.31 216.72,168.34 216.7,168.37 216.68,168.4 216.68,168.45 216.68,168.49 216.73,168.59 216.83,168.62 218.1,168.62 218.38,168.68 218.61,168.84 218.98,169.21 219.03,169.24 219.09,169.25 221.35,169.25 221.46,169.21 221.5,169.1 221.5,162.06 221.49,162 221.46,161.96 221.29,161.79 221.25,161.76 221.19,161.75
N17116652 on TOP: 232.31,168.25 232.25,168.26 232.21,168.29 232.04,168.46 232.01,168.5 232,168.56 232,170.44 232.01,170.5 232.04,170.54 232.21,170.71 232.25,170.74 232.31,170.75 236.59,170.75 236.65,170.74 236.69,170.71 237.11,170.29 237.14,170.25 237.15,170.19 237.15,168.81 237.14,168.75 237.11,168.71 236.69,168.29 236.65,168.26 236.59,168.25
N17116652 on BOTTOM: 231.65,159.5 231.54,159.54 231.5,159.65 231.5,166.5 230.75,167.25 227.75,167.25 226.29,165.79 226.25,165.76 226.19,165.75 225.15,165.75 225.04,165.79 225,165.9 225,168.5 224.5,169 223.65,169 223.54,169.04 223.5,169.15 223.5,169.35 223.54,169.46 223.65,169.5 225,169.5 225.58,169.69 225.94,170.17 226.04,170.27 226.17,170.25 228.85,169.52 231.36,170.7 231.41,170.74 231.47,170.75 236.44,170.75 236.5,170.74 236.54,170.71 237.21,170.04 237.24,170 237.25,169.94 237.25,168.79 237.24,168.73 237.21,168.68 236.79,168.27 236.75,168.24 236.69,168.22 236.2,168.22 235.69,168.14 235.2,167.86 235.15,167.85 235.08,167.85 234.76,167.54 234.47,167.2 234.22,166.87 234,166.51 233.98,166.48 233,165.5 233,160.75 233.46,160.29 233.49,160.25 233.5,160.19 233.5,159.73 233.49,159.67 233.46,159.62 233.38,159.54 233.33,159.51 233.27,159.5
N17116930 on TOP: 265.5,120.75 265.43,120.57 265.25,120.5 251.75,120.5 251.57,120.57 251.5,120.75 251.5,169.25 251.57,169.43 251.75,169.5 265.25,169.5 265.43,169.43 265.5,169.25 ; 11 cut-outs
N17117054 on TOP: 219.48,127.5 219.42,127.51 219.37,127.54 219.25,127.66 218.88,127.91 218.44,128 216.98,128 216.93,128.01 216.87,128.05 216.85,128.05 215.65,128.05 215.54,128.09 215.5,128.2 215.5,129.44 215.51,129.5 215.54,129.54 215.9,129.9 215.9,132.5 215.94,132.61 216.05,132.65 216.6,132.65 216.71,132.61 216.75,132.5 216.83,132.12 217.04,131.79 217.49,131.35 219.3,131.35 219.41,131.31 219.45,131.2 219.45,130.3 220.46,129.29 220.49,129.25 220.5,129.19 220.5,127.81 220.49,127.75 220.46,127.71 220.29,127.54 220.25,127.51 220.19,127.5
N17117347 on BOTTOM: 217.4,120.5 217.29,120.54 217.25,120.65 217.25,121.69 217.26,121.75 217.29,121.79 217.7,122.2 217.7,125.4 217.67,125.52 217.63,125.57 217.54,125.66 217.51,125.7 217.5,125.76 217.5,126.44 217.51,126.5 217.54,126.54 217.71,126.71 217.75,126.74 217.81,126.75 218.19,126.75 218.25,126.74 218.29,126.71 218.46,126.54 218.49,126.5 218.5,126.44 218.5,124.06 218.59,123.62 218.84,123.25 219,123.09 219.37,122.84 219.81,122.75 220.34,122.75 220.4,122.74 220.44,122.71 220.82,122.33 220.84,122.3 220.89,122.18 220.9,122.1 220.9,121.9 220.9,121.86 220.88,121.81 220.85,121.77 219.79,120.71 219.63,120.54 219.58,120.51 219.52,120.5
N17117434 on BOTTOM: 219.81,123.75 219.75,123.76 219.71,123.79 219.54,123.96 219.51,124 219.5,124.06 219.5,127.25 219,127.75 217.81,127.75 217.75,127.76 217.71,127.79 217.54,127.96 217.51,128 217.5,128.06 217.5,129.09 217.41,129.53 217.16,129.9 216.75,130.31 216.72,130.34 216.7,130.37 216.68,130.41 216.68,130.47 216.72,130.58 216.83,130.62 218.1,130.62 218.38,130.68 218.61,130.84 218.98,131.21 219.03,131.24 219.09,131.25 221.35,131.25 221.46,131.21 221.5,131.1 221.5,124.06 221.49,124 221.46,123.96 221.29,123.79 221.25,123.76 221.19,123.75
N17117438 on TOP: 232.31,130.25 232.25,130.26 232.21,130.29 232.04,130.46 232.01,130.5 232,130.56 232,132.44 232.01,132.5 232.04,132.54 232.21,132.71 232.25,132.74 232.31,132.75 236.59,132.75 236.65,132.74 236.69,132.71 237.11,132.29 237.14,132.25 237.15,132.19 237.15,130.81 237.14,130.75 237.11,130.71 236.69,130.29 236.65,130.26 236.59,130.25
